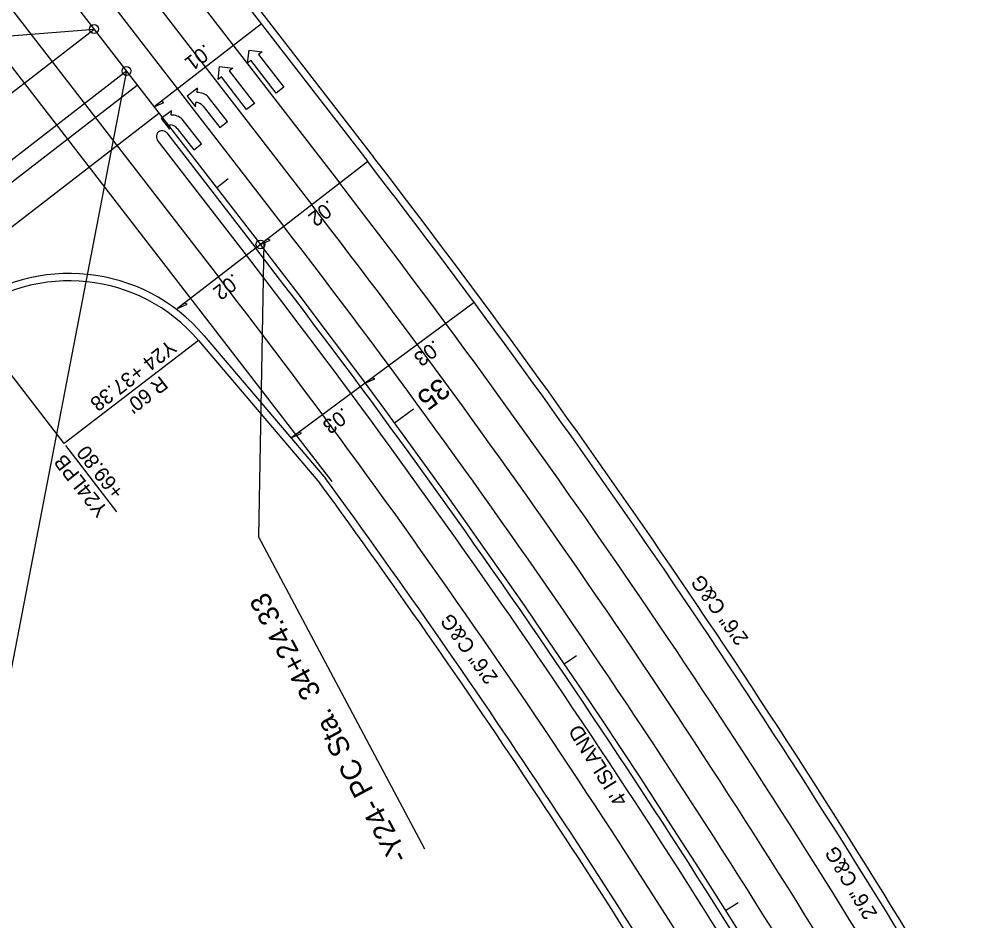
# Model space of a CAD drawing. Extents: x 2389694 to 2405615, y 546931 to 573532.
# Drawn here: x 2402133 to 2402460.2, y 571233.3 to 571539.1 of the extents above; entities that cross this region are included whole.
import ezdxf

# ---------------------------------------------------------------- set-up
doc = ezdxf.new("R2010")
doc.units = 0
for name, color, linetype in [('Prop Conc 2ft 6in Curb and Gutter', 7, 'Continuous'), ('Prop Conc 5in Monolithic Keyed In Island', 7, 'Continuous'), ('Prop Dimension', 7, 'Continuous'), ('Prop Dimension Text', 7, 'Continuous'), ('Prop EOT', 7, 'Continuous'), ('Prop Horizontal Alignment', 7, 'Continuous'), ('Prop Horizontal Alignment Curve and Spiral Data', 7, 'Continuous'), ('Prop Horizontal Alignment Tick Large', 7, 'Continuous'), ('Prop Horizontal Alignment Tick Small', 7, 'Continuous'), ('Prop Lane Arrow Left Turn CELL', 7, 'Continuous'), ('Prop Lane Arrow Right Turn CELL', 7, 'Continuous'), ('Prop Lane Arrow Through CELL', 7, 'Continuous'), ('Prop Lane Lines', 7, 'Continuous'), ('Prop Super Arrow 1 Lane CELL', 7, 'Continuous'), ('Prop Superelevation Label', 7, 'Continuous')]:
    doc.layers.add(name, color=color, linetype=linetype)

msp = doc.modelspace()

# ---------------------------------------------------------------- linework, layer by layer
at = {"layer": 'Prop Conc 2ft 6in Curb and Gutter'}
for p, q in [((2402146.63, 571630.35), (2402253.19, 571492.37)), ((2402193.79, 571430.15), (2402234.96, 571381.78))]:
    msp.add_line(p, q, dxfattribs=at)
for centre, radius, start, end in [((2399929.8, 569697.99), 2935.63, 30.78279, 37.67936), ((2402150, 571392.89), 57.5, 40.4004, 127.6794), ((2399929.8, 569697.99), 2854.63, 30.78279, 36.14596)]:
    msp.add_arc(centre, radius, start, end, dxfattribs=at)
at = {"layer": 'Prop Conc 5in Monolithic Keyed In Island'}
for p, q in [((2402183.06, 571500.55), (2402213.22, 571461.5)), ((2402210.05, 571459.06), (2402179.9, 571498.1)), ((2402210.05, 571459.06), (2402179.9, 571498.1))]:
    msp.add_line(p, q, dxfattribs=at)
for centre, radius, start, end in [((2402181.48, 571499.32), 2, 37.6793, 217.6806), ((2399929.8, 569697.99), 2885.13, 30.78279, 37.67936), ((2399929.8, 569697.99), 2881.13, 30.78279, 37.67936)]:
    msp.add_arc(centre, radius, start, end, dxfattribs=at)
at = {"layer": 'Prop Dimension'}
for p, q in [((2402148.17, 571395.26), (2402114.86, 571438.39)), ((2402193.79, 571430.15), (2402148.17, 571395.26)), ((2402166.08, 571372.08), (2402148.77, 571394.49))]:
    msp.add_line(p, q, dxfattribs=at)
at = {"layer": 'Prop EOT'}
for p, q in [((2402144.65, 571628.82), (2402251.21, 571490.84)), ((2402195.7, 571431.77), (2402236.98, 571383.25))]:
    msp.add_line(p, q, dxfattribs=at)
for centre, radius, start, end in [((2399929.8, 569697.99), 2933.13, 30.78279, 37.67936), ((2402150, 571392.89), 60, 40.3939, 127.6794), ((2399929.8, 569697.99), 2857.13, 30.78279, 36.14596)]:
    msp.add_arc(centre, radius, start, end, dxfattribs=at)
at = {"layer": 'Prop Horizontal Alignment'}
for p, q in [((2401776.58, 572030.14), (2402214.8, 571462.73)), ((2402000.08, 571413.55), (2402158.36, 571535.8)), ((2402027.2, 571411.76), (2402169.37, 571521.56))]:
    msp.add_line(p, q, dxfattribs=at)
msp.add_arc((2399929.8, 569697.99), 2887.13, 22.84477, 37.67936, dxfattribs=at)
at = {"layer": 'Prop Horizontal Alignment Curve and Spiral Data'}
for p, q in [((2401935.87, 571517.67), (2402158.36, 571535.8)), ((2402169.37, 571521.56), (2402113.98, 571234.66)), ((2402215.99, 571463.64), (2402214.12, 571363.68)), ((2402270.55, 571257.55), (2402214.12, 571363.68))]:
    msp.add_line(p, q, dxfattribs=at)
for centre in [(2402158.36, 571535.8), (2402169.37, 571521.56), (2402214.8, 571462.73)]:
    msp.add_circle(centre, 1.5, dxfattribs=at)
at = {"layer": 'Prop Horizontal Alignment Tick Large'}
msp.add_line((2402260.26, 571402.24), (2402266.72, 571406.96), dxfattribs=at)
at = {"layer": 'Prop Horizontal Alignment Tick Small'}
for p, q in [((2402199.93, 571481.98), (2402203.89, 571485.04)), ((2402317.88, 571320.52), (2402322.02, 571323.33)), ((2402372.64, 571236.84), (2402376.87, 571239.51))]:
    msp.add_line(p, q, dxfattribs=at)
at = {"layer": 'Prop Lane Arrow Left Turn CELL'}
for p, q in [((2402184.68, 571508.08), (2402181.18, 571505.41)), ((2402184.5, 571506.6), (2402184.68, 571508.08)), ((2402181.18, 571505.41), (2402183.92, 571501.83)), ((2402183.92, 571501.83), (2402184.1, 571503.31)), ((2402194.78, 571496.88), (2402188.28, 571505.18)), ((2402186.54, 571502.05), (2402192.19, 571494.84)), ((2402192.19, 571494.84), (2402194.78, 571496.88))]:
    msp.add_line(p, q, dxfattribs=at)
for centre, radius, start, end in [((2402184.69, 571501.37), 5.25, 46.7407, 92.0524), ((2402183.97, 571500.05), 3.28, 38.0647, 87.7228)]:
    msp.add_arc(centre, radius, start, end, dxfattribs=at)
at = {"layer": 'Prop Lane Arrow Right Turn CELL'}
for p, q in [((2402193.48, 571515.69), (2402189.99, 571513.01)), ((2402189.99, 571513.01), (2402192.72, 571509.44)), ((2402193.3, 571514.21), (2402193.48, 571515.69)), ((2402203.59, 571504.48), (2402197.08, 571512.79)), ((2402192.72, 571509.44), (2402192.9, 571510.91)), ((2402195.35, 571509.65), (2402200.99, 571502.45)), ((2402200.99, 571502.45), (2402203.59, 571504.48))]:
    msp.add_line(p, q, dxfattribs=at)
for centre, radius, start, end in [((2402193.5, 571508.98), 5.25, 46.7407, 92.0524), ((2402192.78, 571507.65), 3.28, 38.0647, 87.7228)]:
    msp.add_arc(centre, radius, start, end, dxfattribs=at)
at = {"layer": 'Prop Lane Arrow Through CELL'}
for p, q in [((2402210.39, 571524.26), (2402210.93, 571528.65)), ((2402210.93, 571528.65), (2402215.38, 571528.1)), ((2402215.38, 571528.1), (2402214.19, 571527.19)), ((2402214.19, 571527.19), (2402222.72, 571516.08)), ((2402200.42, 571518.72), (2402200.96, 571523.1)), ((2402200.96, 571523.1), (2402205.41, 571522.56)), ((2402205.41, 571522.56), (2402204.23, 571521.64)), ((2402211.58, 571525.18), (2402210.39, 571524.26)), ((2402220.1, 571514.07), (2402211.58, 571525.18)), ((2402201.61, 571519.63), (2402200.42, 571518.72)), ((2402210.13, 571508.53), (2402201.61, 571519.63)), ((2402204.23, 571521.64), (2402212.75, 571510.54)), ((2402222.72, 571516.08), (2402220.1, 571514.07)), ((2402212.75, 571510.54), (2402210.13, 571508.53))]:
    msp.add_line(p, q, dxfattribs=at)
at = {"layer": 'Prop Lane Lines'}
for p, q in [((2401762.33, 572019.14), (2402200.56, 571451.72)), ((2401962.25, 571740.65), (2402239.02, 571382.28)), ((2402135.15, 571621.48), (2402241.71, 571483.51)), ((2402125.65, 571614.15), (2402232.21, 571476.17)), ((2402116.16, 571606.81), (2402222.72, 571468.84)), ((2402030.87, 571407.01), (2402173.03, 571516.81)), ((2402038.2, 571397.51), (2402180.37, 571507.31))]:
    msp.add_line(p, q, dxfattribs=at)
for radius, start in [(2921.13, 30.86392), (2909.13, 30.96433), (2897.13, 30.86392), (2869.13, 30.9716)]:
    msp.add_arc((2399929.8, 569697.99), radius, start, 37.67936, dxfattribs=at)
at = {"layer": 'Prop Super Arrow 1 Lane CELL'}
for p, q in [((2402215.14, 571537.54), (2402178.74, 571509.42)), ((2402251.21, 571490.85), (2402214.8, 571462.73)), ((2402214.8, 571462.73), (2402186.64, 571440.98)), ((2402287.36, 571443.04), (2402250.38, 571415.67)), ((2402250.38, 571415.67), (2402225.47, 571397.22))]:
    msp.add_line(p, q, dxfattribs=at)
for points in [[(2402178.74, 571509.42), (2402182, 571510.93), (2402181.07, 571511.23)], [(2402214.8, 571462.73), (2402218.06, 571464.23), (2402217.14, 571464.53)], [(2402186.64, 571440.98), (2402189.9, 571442.49), (2402188.98, 571442.78)], [(2402250.38, 571415.67), (2402253.67, 571417.11), (2402252.76, 571417.42)], [(2402225.47, 571397.22), (2402228.76, 571398.66), (2402227.84, 571398.98)]]:
    msp.add_lwpolyline(points, close=True, dxfattribs=at)

# ---------------------------------------------------------------- texts
at = {"layer": 'Prop Dimension Text'}
for s, rotation, p in [('2\'6" C&G', 126.1958, (2402380.63, 571329.06)), ('2\'6" C&G', 126.1958, (2402295.63, 571315.9)), ("4' ISLAND", 121.8856, (2402339.6, 571274.05)), ('2\'6" C&G', 120.903, (2402424.3, 571235.64))]:
    msp.add_text(s, height=5, rotation=rotation, dxfattribs=at).set_placement(p)
at = {"layer": 'Prop Horizontal Alignment Curve and Spiral Data'}
for s, rotation, p in [('35', 216.1777, (2402275.74, 571417.83)), ('-Y24- PC Sta.  34+24.33', 118.2242, (2402265.33, 571255.13))]:
    msp.add_text(s, height=7, rotation=rotation, dxfattribs=at).set_placement(p)
at = {"layer": 'Prop Super Arrow 1 Lane CELL'}
for s, rotation, p in [('Y24 +37.38', 217.6796, (2402183.79, 571430.73)), ("R 60'", 217.6796, (2402180.89, 571418.38)), ('+69.80', 128.3536, (2402168.8, 571378.86)), ('Y24LPB', 128.3536, (2402163.42, 571372.77))]:
    msp.add_text(s, height=5, rotation=rotation, dxfattribs=at).set_placement(p)
at = {"layer": 'Prop Superelevation Label'}
for s, rotation, p in [('.01', 217.679, (2402196.02, 571530.93)), ('.02', 217.6794, (2402237.92, 571478.06)), ('.02', 217.6796, (2402205.64, 571453.12)), ('.03', 216.5092, (2402273.84, 571430.54)), ('.03', 216.508, (2402242.9, 571407.64))]:
    msp.add_text(s, height=5, rotation=rotation, dxfattribs=at).set_placement(p)

doc.saveas('drawing.dxf')
